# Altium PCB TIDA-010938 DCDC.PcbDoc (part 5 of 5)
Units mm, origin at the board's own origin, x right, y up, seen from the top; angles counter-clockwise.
Board outline 275 x 165 mm, 4 copper layers (Top Layer, Layer 1, Layer 2, Bottom Layer), stack 1.787 mm thick; 436 components, 216 nets, 1367 pads, 1992 vias.
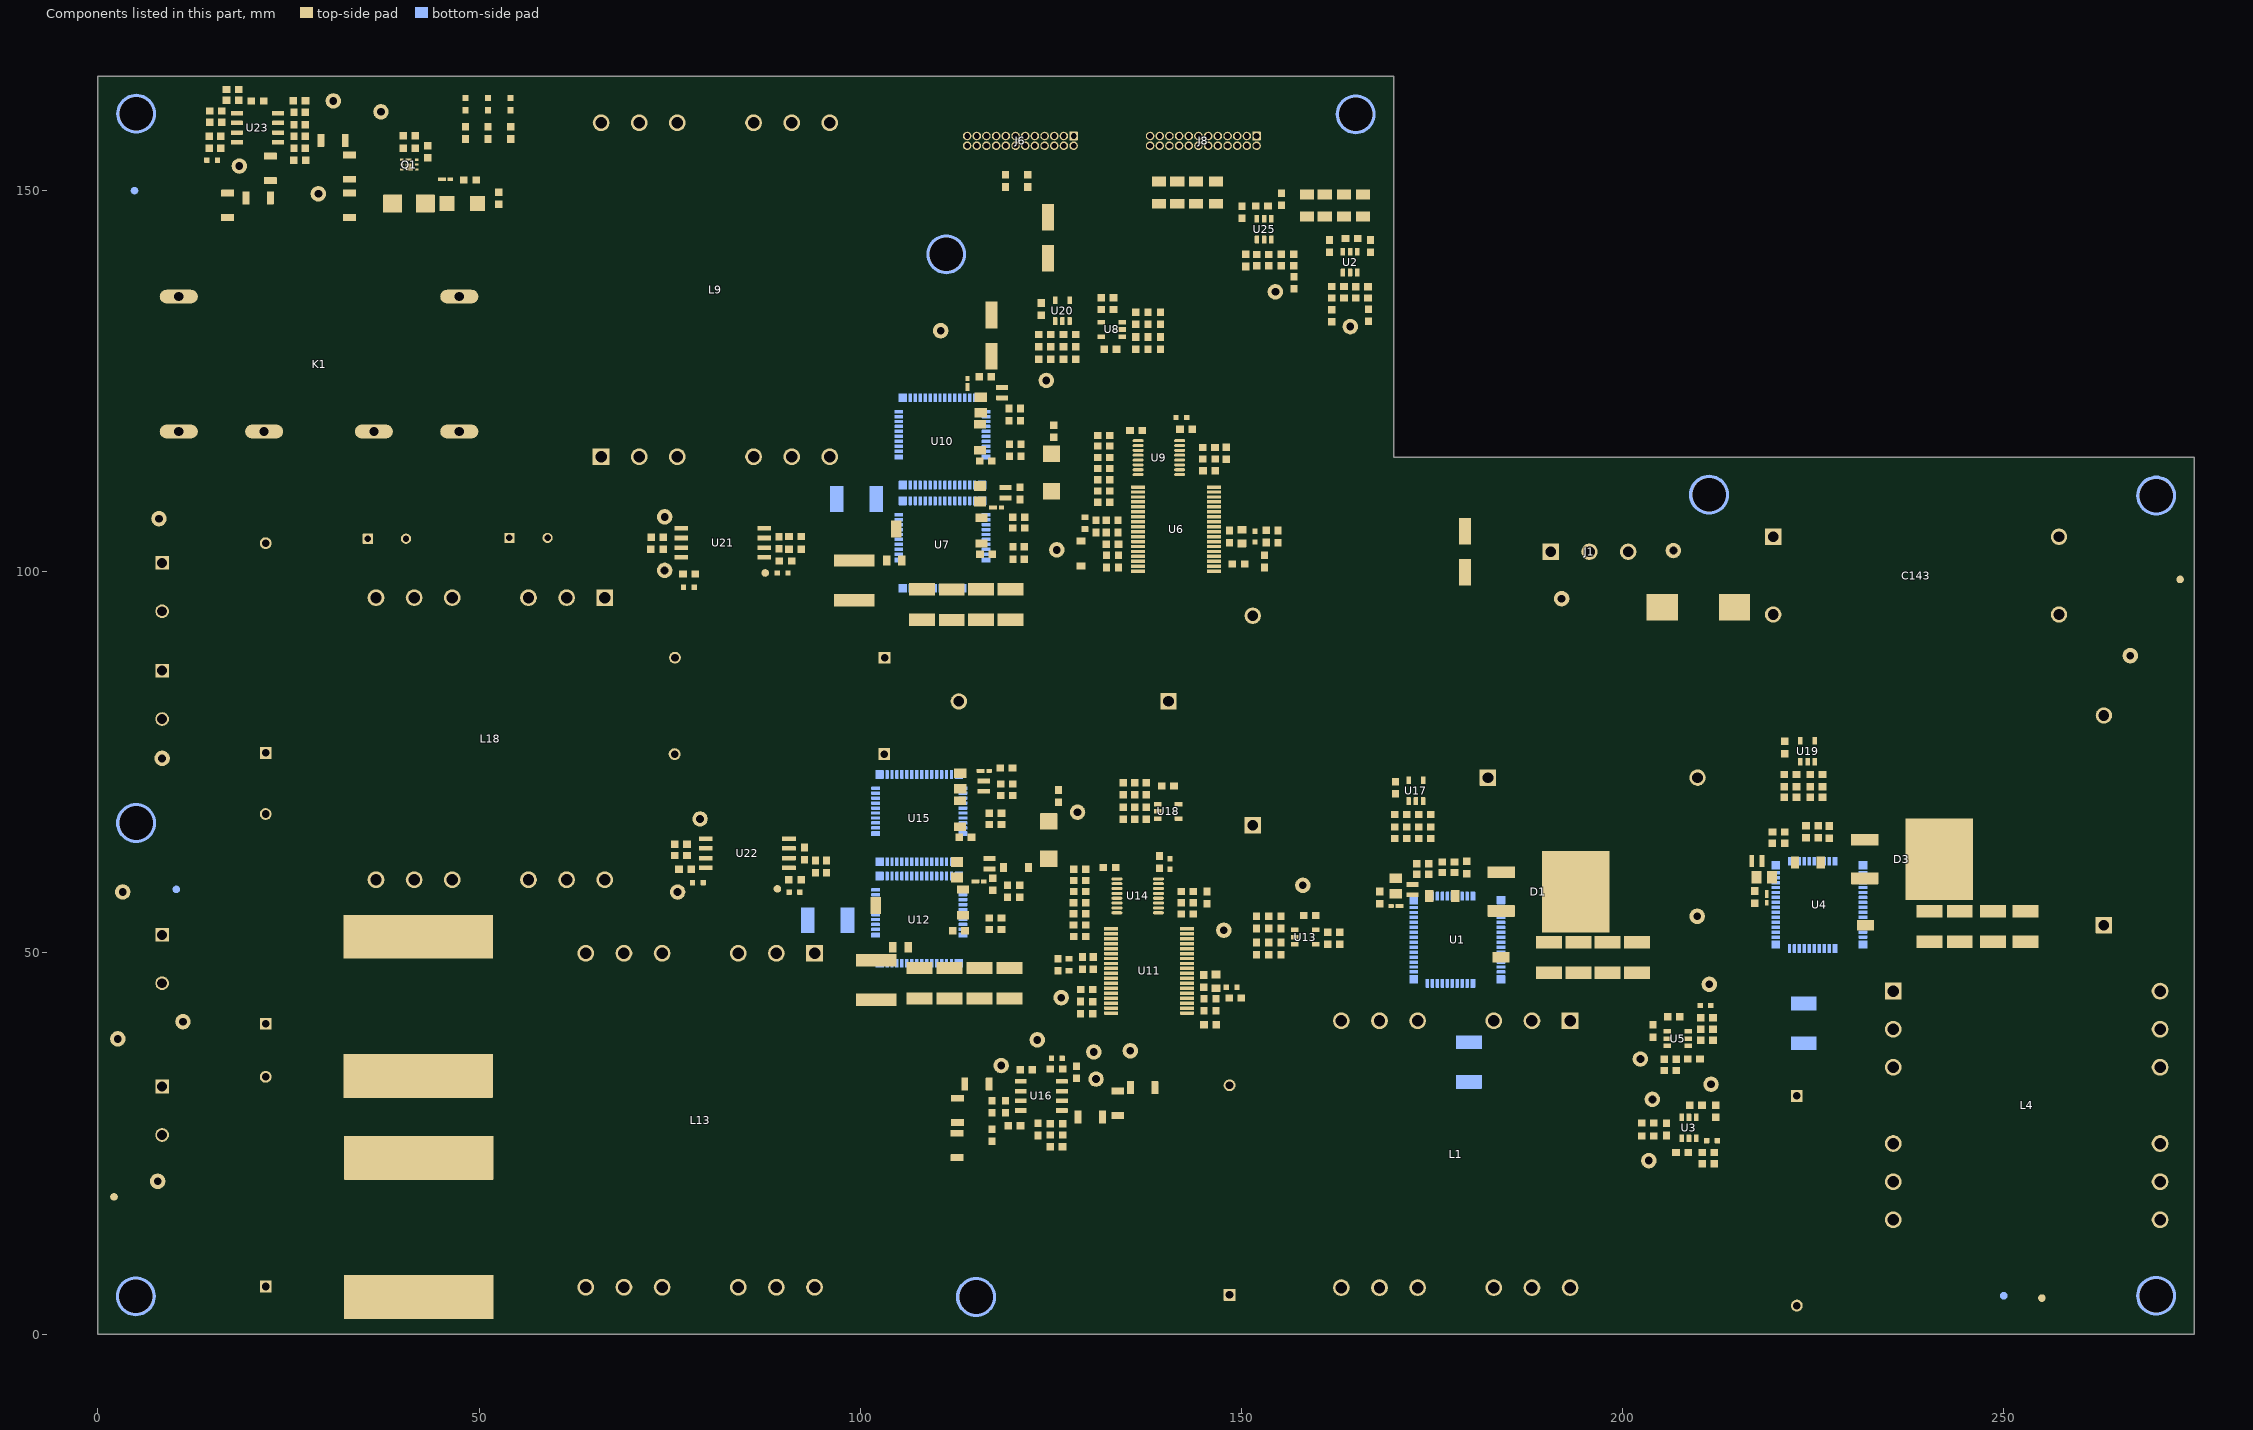
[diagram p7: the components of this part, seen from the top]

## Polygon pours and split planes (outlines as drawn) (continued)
DC_Bus+ on Layer 1 "LAYER_1_DC_BUS+_P054" (solid, remove dead copper, pour order 54): 188.517,68.5 182.279,62.262 182.279,61.241 183.522,59.998 187.559,59.998 189.178,58.378 189.178,51.538 190.472,50.244 203.361,50.244 205.006,51.889 205.006,64.968 201.473,68.5
NetD3_2 on Layer 1 "LAYER_1_NETD3_2_P078" (solid, remove dead copper, pour order 78): 229.901,60.523 229,59.991 229,40 231.216,38.016 237.984,38.016 237.984,41.697 237.984,47.016 234.458,49.649 234.458,59.502 233.485,60.557 233.462,60.535 230.115,60.535
NetD1_2 on Layer 1 "Top Layer-NetD1_2" (solid, remove dead copper, pour order 95): 20 vertices, not listed, extent 181.579,37.987 195.003,56.767
"PV2 Bus-" on Layer 1 "LAYER_1_PV2_BUS-_P001" (solid, remove dead copper, pour order 1): 26 vertices, not listed, extent 1.852,1 229,37.513
Boost1_IN+ on Layer 1 "LAYER_1_BOOST1_IN+_P166" (solid, remove dead copper, pour order 166): 22 vertices, not listed, extent 1.092,46 55.058,70
SW1 on Layer 1 "LAYER_1_SW1_P170" (solid, remove dead copper, pour order 170): 19 vertices, not listed, extent 114.052,100.143 137.625,118.679
SW2 on Layer 1 "LAYER_1_SW2_P174" (solid, remove dead copper, pour order 174): 95.142,57.276 89.165,57.276 88,58.441 88,67.708 88.559,68.267 92.692,68.267 97.153,63.806 97.153,59.288
SW1 on Layer 1 "LAYER_1_SW1_P173" (solid, remove dead copper, pour order 173): 92.907,97.929 86.93,97.929 85.394,99.465 85.394,107.99 86.324,108.92 92.647,108.92 94.918,106.649 94.918,99.94
DC_Bus+ on Layer 1 "LAYER_1_DC_BUS+_P025" (solid, remove dead copper, pour order 25): 37 vertices, not listed, extent 96.725,47.578 144.934,101.04
SW2 on Layer 1 "LAYER_1_SW2_P171" (solid, remove dead copper, pour order 171): 20 vertices, not listed, extent 111.312,41.64 135.151,64.322
DC_Bus- on Bottom Layer "Bottom_Layer-Bat_IN-" (solid, remove dead copper, pour order 163): 112.264,72.123 109.957,74.429 109.957,91.115 122.578,91.115 122.578,93.784 121.782,94.58 104.964,94.58 99.731,89.347 99.731,66.168 111.754,66.168 112.264,66.62
GND_HVN on Bottom Layer "Bottom Layer-GND_HVN" (solid, remove dead copper, pour order 158): 39 vertices, not listed, extent 7.089,56.427 114.316,164.604
DC_Bus+ on Bottom Layer "Bottom Layer-DC_Bus+" (solid, remove dead copper, pour order 55): 54 vertices, not listed, extent 130.01,50.244 273.516,110.074
NetD3_2 on Bottom Layer "Bottom Layer-NetD3_2" (solid, remove dead copper, pour order 74): 229.382,39.41 231.276,37.515 237.923,37.515 238.541,38.133 238.541,48.198 236.964,49.775 233.84,49.775 233.84,60.202 233.193,60.849 230.226,60.849 229.382,60.005 229.382,48.198 229.382,46.083
"BAT Bus-" on Bottom Layer "BOTTOM_LAYER_BAT_BUS-_P108" (solid, remove dead copper, pour order 108): 36 vertices, not listed, extent 3.39,73.669 56.475,121
SW1 on Bottom Layer "BOTTOM_LAYER_SW1_P022" (solid, remove dead copper, pour order 22): 137.536,115.654 137.625,100.293 137.475,100.143 124.644,100.143 123.158,101.59 119.548,101.59 119.548,112.27 125.326,112.27 128.499,115.443 128.499,116.605 130.573,118.679 137.536,118.679
SW2 on Bottom Layer "BOTTOM_LAYER_SW2_P015" (solid, remove dead copper, pour order 15): 17 vertices, not listed, extent 116.501,41.64 135.151,64.322
SW2 on Bottom Layer "gan1_sw" (solid, remove dead copper, pour order 118): 23 vertices, not listed, extent 88,52.689 112.761,68.291
SW1 on Bottom Layer "gan2_sw" (solid, remove dead copper, pour order 119): 38 vertices, not listed, extent 85.394,97.929 115.5,112.356
BatIN+ on Bottom Layer "BOTTOM_LAYER_BATIN+_P169" (solid, remove dead copper, pour order 169): 33 vertices, not listed, extent 54,45 78.17,119
DC_Bus- on Bottom Layer "BOTTOM_LAYER_DC_BUS-_P046" (solid, remove dead copper, pour order 46): 217.556,49.537 219.08,48.014 227.382,48.014 227.382,59.806 226.164,61.183 222.664,61.183 220.93,59.526 219.768,59.526 217.556,57.314
NetL9_6 on Bottom Layer "BOTTOM_LAYER_NETL9_6_P099" (solid, remove dead copper, pour order 99): 97.541,107.2 97.259,106.918 94.437,106.918 94.437,115.717 95.425,116.704 97.541,116.704 98.491,115.754 98.491,113.733 97.541,112.783 97.541,112.699
DC_Bus- on Bottom Layer "BOTTOM_LAYER_DC_BUS-_P061" (solid, remove dead copper, pour order 61): 102.189,124.254 103.532,125.597 111.707,125.597 114,123.304 114,122.013 114.009,122.013 114.446,121.556 114.446,116.796 113.049,115.561 103.421,115.561 102.189,116.793
DC_Bus- on Bottom Layer "BOTTOM_LAYER_DC_BUS-_P125" (solid, remove dead copper, pour order 125): 149.167,54.394 150.112,53.467 150.112,49.67 148.362,47.92 148.362,46.67 142.862,46.67 142.862,53.627 142.679,53.809 140.04,53.809 138.45,55.4 138.499,55.45 140.058,55.45 141.139,54.368 141.165,54.394
DC_Bus+ on Bottom Layer "BOTTOM_LAYER_DC_BUS+_P027" (solid, remove dead copper, pour order 27): 105.788,50.104 107.03,51.346 107.03,51.419 109.35,51.419 110.2,50.57 120.43,50.57 120.43,47.125 103.271,47.125 103.271,49.788 103.586,50.104
DC_Bus- on Bottom Layer "BOTTOM_LAYER_DC_BUS-_P045" (solid, remove dead copper, pour order 45): 180.113,46.777 179.937,46.6 179.991,46.546 179.991,44.35 171.785,44.35 170.348,45.787 170.348,53.998 171.293,54.942 173.254,54.942 173.661,55.349 175.145,56.767 178.342,56.767 180.113,54.765
"PV1 Bus+" on Bottom Layer "BOTTOM_LAYER_PV1_BUS+_P003" (solid, remove dead copper, pour order 3): 18 vertices, not listed, extent 30.975,12.957 170,43.263
DC_Bus+ on Bottom Layer "BOTTOM_LAYER_DC_BUS+_P120" (solid, remove dead copper, pour order 120): 104.315,99.87 110.21,99.87 110.987,100.647 113.839,100.647 115.323,99.163 122.21,99.163 122.845,98.528 122.845,96.334 118.152,96.334 118.145,96.341 116.775,96.341 105.141,96.341 103.806,97.675 103.806,99.362
NetL13_1 on Bottom Layer "BOTTOM_LAYER_NETL13_1_P085" (solid, remove dead copper, pour order 85): 96.381,50.591 96.381,48.636 95.219,47.474 92.464,47.474 92.464,47.494 91.392,48.566 91.392,50.463 90.304,51.55 90.304,54.676 91.437,55.808 94,55.808 94,52.972
Boost1_IN+ on Bottom Layer "BOTTOM_LAYER_BOOST1_IN+_P110" (solid, remove dead copper, pour order 110): 22 vertices, not listed, extent 1.092,46 55.058,70
NetD1_2 on Bottom Layer "Bottom Layer-NetD1_2" (solid, remove dead copper, pour order 97): 21 vertices, not listed, extent 181.711,37.987 195.003,56.767
DC_Bus- on Bottom Layer "BOTTOM_LAYER_DC_BUS-_P071" (solid, remove dead copper, pour order 71): 178.237,38.041 177.936,38.342 177.936,40.037 178.668,40.769 180.931,40.769 181.656,40.045 181.656,38.236 181.461,38.041
DC_Bus- on Bottom Layer "BOTTOM_LAYER_DC_BUS-_P068" (solid, remove dead copper, pour order 68): 222.579,43.014 221.926,43.668 221.926,45.363 222.658,46.095 224.921,46.095 225.646,45.37 225.646,43.562 225.097,43.014
"PV2 Bus-" on Bottom Layer "BOTTOM_LAYER_PV2_BUS-_P069" (solid, remove dead copper, pour order 69): 225.42,38.329 225.721,38.028 225.721,36.333 224.989,35.601 222.726,35.601 222.001,36.325 222.001,38.134 222.196,38.329
"PV1 Bus-" on Bottom Layer "BOTTOM_LAYER_PV1_BUS-_P072" (solid, remove dead copper, pour order 72): 180.954,33.48 181.731,32.703 181.731,31.007 180.999,30.275 178.736,30.275 178.012,31 178.012,32.808 178.683,33.48
"BAT Bus+" on Layer 2 (solid, remove dead copper, pour order 191): 18 vertices, not listed, extent 4.993,92.39 18,146.815
DC_Bus- on Layer 2 (solid, remove dead copper, pour order 190): 83 vertices, not listed, extent 111.006,24.738 272.847,107.006
GND_HVN on Layer 2 "LAYER_2_GND_HVN_P147" (solid, remove dead copper, pour order 147): 20 vertices, not listed, extent 121.011,90.981 179.226,154.748
DC_Bus- on Layer 2 "Layer 2-Bat_IN-" (solid, remove dead copper, pour order 40): 36 vertices, not listed, extent 94.909,41.29 121.818,125.597
BatIN+ on Layer 2 "LAYER_2_BATIN+_P008" (solid, remove dead copper, pour order 8): 33 vertices, not listed, extent 54,45 78.17,119
"PV1 Bus-" on Layer 2 "LAYER_2_PV1_BUS-_P004" (solid, remove dead copper, pour order 4): 31 vertices, not listed, extent 4.6,2 187,48.5
"BAT Bus-" on Layer 2 "LAYER_2_BAT_BUS-_P117" (solid, remove dead copper, pour order 117): 34.018,120 34.075,120.057 39.036,120.057 39.036,120.014 40.05,119 40.05,117.014 39.036,116 33.024,116 33.024,116.006 32.029,117 32.029,127.753 32.029,146.556 33.904,146.556 34.018,146.443
NetC2_2 on Layer 2 "LAYER_2_NETC2_2_P132" (solid, remove dead copper, pour order 132): 19 vertices, not listed, extent 18,94.007 49,121
no net on Bottom Solder "BOTTOM_LAYER_NONET_P106" (solid): 201.815,90.575 207.571,84.818 207.571,55.048 203.065,50.542 189.677,50.542 188.455,51.763 188.455,90.575
no net on Bottom Solder "BOTTOM_LAYER_NONET_P106" (solid): 249.592,95.094 255.349,89.338 255.349,59.568 250.842,55.061 237.454,55.061 236.232,56.283 236.232,95.094

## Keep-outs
Keep-Out Layer:
  the board outline again, w0.5

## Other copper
Top Layer:
  pour cut-out: 211.324,103.147 cw(c211.324,110.147) 204.324,110.147 cw(c211.324,110.147) 211.324,117.147 cw(c211.324,110.147) 218.324,110.147 cw(c211.324,110.147)
  pour cut-out: 75.693,73.082 cw(c75.693,76.082) 72.693,76.082 cw(c75.693,76.082) 75.693,79.082 cw(c75.693,76.082) 78.693,76.082 cw(c75.693,76.082)
  pour cut-out: 75.743,85.73 cw(c75.743,88.73) 72.743,88.73 cw(c75.743,88.73) 75.743,91.73 cw(c75.743,88.73) 78.743,88.73 cw(c75.743,88.73)
  pour cut-out: 111.208,134.727 cw(c111.208,141.727) 104.208,141.727 cw(c111.208,141.727) 111.208,148.727 cw(c111.208,141.727) 118.208,141.727 cw(c111.208,141.727)
  pour cut-out: 151.46,59.762 cw(c151.46,66.762) 144.46,66.762 cw(c151.46,66.762) 151.46,73.762 cw(c151.46,66.762) 158.46,66.762 cw(c151.46,66.762)
  pour cut-out: 111.184,4.869 ccw(c115.184,4.869) 115.184,0.869 ccw(c115.184,4.869) 119.184,4.869 ccw(c115.184,4.869) 115.184,8.869 ccw(c115.184,4.869)
  pour cut-out: 90,49.958 ccw(c94,49.958) 94,45.958 ccw(c94,49.958) 98,49.958 ccw(c94,49.958) 94,53.958 ccw(c94,49.958)
  pour cut-out: 60,49.958 ccw(c64,49.958) 64,45.958 ccw(c64,49.958) 68,49.958 ccw(c64,49.958) 64,53.958 ccw(c64,49.958)
  pour cut-out: 85,49.958 ccw(c89,49.958) 89,45.958 ccw(c89,49.958) 93,49.958 ccw(c89,49.958) 89,53.958 ccw(c89,49.958)
  pour cut-out: 80,49.958 ccw(c84,49.958) 84,45.958 ccw(c84,49.958) 88,49.958 ccw(c84,49.958) 84,53.958 ccw(c84,49.958)
  pour cut-out: 70,49.958 ccw(c74,49.958) 74,45.958 ccw(c74,49.958) 78,49.958 ccw(c74,49.958) 74,53.958 ccw(c74,49.958)
  pour cut-out: 65,49.958 ccw(c69,49.958) 69,45.958 ccw(c69,49.958) 73,49.958 ccw(c69,49.958) 69,53.958 ccw(c69,49.958)
  pour cut-out: 62.475,59.611 ccw(c66.475,59.611) 66.475,55.611 ccw(c66.475,59.611) 70.475,59.611 ccw(c66.475,59.611) 66.475,63.611 ccw(c66.475,59.611)
  pour cut-out: 57.475,59.611 ccw(c61.475,59.611) 61.475,55.611 ccw(c61.475,59.611) 65.475,59.611 ccw(c61.475,59.611) 61.475,63.611 ccw(c61.475,59.611)
  pour cut-out: 52.475,59.611 ccw(c56.475,59.611) 56.475,55.611 ccw(c56.475,59.611) 60.475,59.611 ccw(c56.475,59.611) 56.475,63.611 ccw(c56.475,59.611)
  pour cut-out: 218.857,31.246 ccw(c222.857,31.246) 222.857,27.246 ccw(c222.857,31.246) 226.857,31.246 ccw(c222.857,31.246) 222.857,35.246 ccw(c222.857,31.246)
  pour cut-out: 164.11,41.1 ccw(c168.11,41.1) 168.11,37.1 ccw(c168.11,41.1) 172.11,41.1 ccw(c168.11,41.1) 168.11,45.1 ccw(c168.11,41.1)
  pour cut-out: 159.11,41.1 ccw(c163.11,41.1) 163.11,37.1 ccw(c163.11,41.1) 167.11,41.1 ccw(c163.11,41.1) 163.11,45.1 ccw(c163.11,41.1)
  pour cut-out: 169.11,41.1 ccw(c173.11,41.1) 173.11,37.1 ccw(c173.11,41.1) 177.11,41.1 ccw(c173.11,41.1) 173.11,45.1 ccw(c173.11,41.1)
  pour cut-out: 266.503,45 ccw(c270.503,45) 270.503,41 ccw(c270.503,45) 274.503,45 ccw(c270.503,45) 270.503,49 ccw(c270.503,45)
  pour cut-out: 266.503,40 ccw(c270.503,40) 270.503,36 ccw(c270.503,40) 274.503,40 ccw(c270.503,40) 270.503,44 ccw(c270.503,40)
  pour cut-out: 266.503,35 ccw(c270.503,35) 270.503,31 ccw(c270.503,35) 274.503,35 ccw(c270.503,35) 270.503,39 ccw(c270.503,35)
  pour cut-out: 266.503,25 ccw(c270.503,25) 270.503,21 ccw(c270.503,25) 274.503,25 ccw(c270.503,25) 270.503,29 ccw(c270.503,25)
  pour cut-out: 266.503,20 ccw(c270.503,20) 270.503,16 ccw(c270.503,20) 274.503,20 ccw(c270.503,20) 270.503,24 ccw(c270.503,20)
  pour cut-out: 266.503,15 ccw(c270.503,15) 270.503,11 ccw(c270.503,15) 274.503,15 ccw(c270.503,15) 270.503,19 ccw(c270.503,15)
  pour cut-out: 144.439,5.144 ccw(c148.439,5.144) 148.439,1.144 ccw(c148.439,5.144) 152.439,5.144 ccw(c148.439,5.144) 148.439,9.144 ccw(c148.439,5.144)
  pour cut-out: 3.8,26.125 ccw(c7.8,26.125) 7.8,22.125 ccw(c7.8,26.125) 11.8,26.125 ccw(c7.8,26.125) 7.8,30.125 ccw(c7.8,26.125)
  pour cut-out: 18,40.725 ccw(c22,40.725) 22,36.725 ccw(c22,40.725) 26,40.725 ccw(c22,40.725) 22,44.725 ccw(c22,40.725)
  pour cut-out: 87,114.832 ccw(c91,114.832) 91,110.832 ccw(c91,114.832) 95,114.832 ccw(c91,114.832) 91,118.832 ccw(c91,114.832)
  pour cut-out: 82,115.1 ccw(c86,115.1) 86,111.1 ccw(c86,115.1) 90,115.1 ccw(c86,115.1) 86,119.1 ccw(c86,115.1)
  pour cut-out: 72,115.1 ccw(c76,115.1) 76,111.1 ccw(c76,115.1) 80,115.1 ccw(c76,115.1) 76,119.1 ccw(c76,115.1)
  pour cut-out: 67,115.1 ccw(c71,115.1) 71,111.1 ccw(c71,115.1) 75,115.1 ccw(c71,115.1) 71,119.1 ccw(c71,115.1)
  pour cut-out: 92,158.9 ccw(c96,158.9) 96,154.9 ccw(c96,158.9) 100,158.9 ccw(c96,158.9) 96,162.9 ccw(c96,158.9)
  pour cut-out: 87,158.9 ccw(c91,158.9) 91,154.9 ccw(c91,158.9) 95,158.9 ccw(c91,158.9) 91,162.9 ccw(c91,158.9)
  pour cut-out: 82,158.9 ccw(c86,158.9) 86,154.9 ccw(c86,158.9) 90,158.9 ccw(c86,158.9) 86,162.9 ccw(c86,158.9)
  pour cut-out: 72,158.9 ccw(c76,158.9) 76,154.9 ccw(c76,158.9) 80,158.9 ccw(c76,158.9) 76,162.9 ccw(c76,158.9)
  pour cut-out: 67,158.9 ccw(c71,158.9) 71,154.9 ccw(c71,158.9) 75,158.9 ccw(c71,158.9) 71,162.9 ccw(c71,158.9)
  pour cut-out: 62,158.9 ccw(c66,158.9) 66,154.9 ccw(c66,158.9) 70,158.9 ccw(c66,158.9) 66,162.9 ccw(c66,158.9)
  pour cut-out: 4.881,60.17 cw(c4.881,67.17) -2.119,67.17 cw(c4.881,67.17) 4.881,74.17 cw(c4.881,67.17) 11.881,67.17 cw(c4.881,67.17)
  pour cut-out: 4.948,153.163 cw(c4.948,160.163) -2.052,160.163 cw(c4.948,160.163) 4.948,167.163 cw(c4.948,160.163) 11.948,160.163 cw(c4.948,160.163)
  pour cut-out: 4.952,-2.016 cw(c4.952,4.984) -2.048,4.984 cw(c4.952,4.984) 4.952,11.984 cw(c4.952,4.984) 11.952,4.984 cw(c4.952,4.984)
  pour cut-out: 269.911,-1.891 cw(c269.911,5.109) 262.911,5.109 cw(c269.911,5.109) 269.911,12.109 cw(c269.911,5.109) 276.911,5.109 cw(c269.911,5.109)
  pour cut-out: 269.981,103.024 cw(c269.981,110.024) 262.981,110.024 cw(c269.981,110.024) 269.981,117.024 cw(c269.981,110.024) 276.981,110.024 cw(c269.981,110.024)
  pour cut-out: 164.966,153.041 cw(c164.966,160.041) 157.966,160.041 cw(c164.966,160.041) 164.966,167.041 cw(c164.966,160.041) 171.966,160.041 cw(c164.966,160.041)
  pour cut-out: 115.165,-2.107 cw(c115.165,4.893) 108.165,4.893 cw(c115.165,4.893) 115.165,11.893 cw(c115.165,4.893) 122.165,4.893 cw(c115.165,4.893)
  pour cut-out: 51.753,106.681 56.197,106.681 56.253,106.625 56.253,102.202 51.793,102.202
  pour cut-out: 160.282,9.273 160.282,2.927 196.124,2.927 196.124,9.273
  pour cut-out: 61.172,9.331 61.172,2.985 97.014,2.985 97.014,9.331
  pour cut-out: 38.41,106.443 42.789,106.443 42.845,106.387 42.845,102.077 38.507,102.077 38.424,102.16
  text ".Layer_Name" at -2.5,-161.806 h1.52
Layer 1:
  pour cut-out: 111.184,4.869 ccw(c115.184,4.869) 115.184,0.869 ccw(c115.184,4.869) 119.184,4.869 ccw(c115.184,4.869) 115.184,8.869 ccw(c115.184,4.869)
  pour cut-out: 112.933,81 cw(c112.933,83) 110.933,83 cw(c112.933,83) 112.933,85 cw(c112.933,83) 114.933,83 cw(c112.933,83)
  pour cut-out: 111.261,138.703 cw(c111.261,141.703) 108.261,141.703 cw(c111.261,141.703) 111.261,144.703 cw(c111.261,141.703) 114.261,141.703 cw(c111.261,141.703)
  pour cut-out: 5.001,157.139 cw(c5.001,160.139) 2.001,160.139 cw(c5.001,160.139) 5.001,163.139 cw(c5.001,160.139) 8.001,160.139 cw(c5.001,160.139)
  pour cut-out: 147.479,66.738 ccw(c151.479,66.738) 151.479,62.738 ccw(c151.479,66.738) 155.479,66.738 ccw(c151.479,66.738) 151.479,70.738 ccw(c151.479,66.738)
  pour cut-out: 111.184,4.869 ccw(c115.184,4.869) 115.184,0.869 ccw(c115.184,4.869) 119.184,4.869 ccw(c115.184,4.869) 115.184,8.869 ccw(c115.184,4.869)
  pour cut-out: 90,49.958 ccw(c94,49.958) 94,45.958 ccw(c94,49.958) 98,49.958 ccw(c94,49.958) 94,53.958 ccw(c94,49.958)
  pour cut-out: 60,49.958 ccw(c64,49.958) 64,45.958 ccw(c64,49.958) 68,49.958 ccw(c64,49.958) 64,53.958 ccw(c64,49.958)
  pour cut-out: 85,49.958 ccw(c89,49.958) 89,45.958 ccw(c89,49.958) 93,49.958 ccw(c89,49.958) 89,53.958 ccw(c89,49.958)
  pour cut-out: 80,49.958 ccw(c84,49.958) 84,45.958 ccw(c84,49.958) 88,49.958 ccw(c84,49.958) 84,53.958 ccw(c84,49.958)
  pour cut-out: 70,49.958 ccw(c74,49.958) 74,45.958 ccw(c74,49.958) 78,49.958 ccw(c74,49.958) 74,53.958 ccw(c74,49.958)
  pour cut-out: 65,49.958 ccw(c69,49.958) 69,45.958 ccw(c69,49.958) 73,49.958 ccw(c69,49.958) 69,53.958 ccw(c69,49.958)
  pour cut-out: 231.503,20 ccw(c235.503,20) 235.503,16 ccw(c235.503,20) 239.503,20 ccw(c235.503,20) 235.503,24 ccw(c235.503,20)
  pour cut-out: 231.503,15 ccw(c235.503,15) 235.503,11 ccw(c235.503,15) 239.503,15 ccw(c235.503,15) 235.503,19 ccw(c235.503,15)
  pour cut-out: 218.857,3.746 ccw(c222.857,3.746) 222.857,-0.254 ccw(c222.857,3.746) 226.857,3.746 ccw(c222.857,3.746) 222.857,7.746 ccw(c222.857,3.746)
  pour cut-out: 164.11,41.1 ccw(c168.11,41.1) 168.11,37.1 ccw(c168.11,41.1) 172.11,41.1 ccw(c168.11,41.1) 168.11,45.1 ccw(c168.11,41.1)
  pour cut-out: 159.11,41.1 ccw(c163.11,41.1) 163.11,37.1 ccw(c163.11,41.1) 167.11,41.1 ccw(c163.11,41.1) 163.11,45.1 ccw(c163.11,41.1)
  pour cut-out: 169.11,41.1 ccw(c173.11,41.1) 173.11,37.1 ccw(c173.11,41.1) 177.11,41.1 ccw(c173.11,41.1) 173.11,45.1 ccw(c173.11,41.1)
  pour cut-out: 231.503,25 ccw(c235.503,25) 235.503,21 ccw(c235.503,25) 239.503,25 ccw(c235.503,25) 235.503,29 ccw(c235.503,25)
  pour cut-out: 266.503,45 ccw(c270.503,45) 270.503,41 ccw(c270.503,45) 274.503,45 ccw(c270.503,45) 270.503,49 ccw(c270.503,45)
  pour cut-out: 266.503,40 ccw(c270.503,40) 270.503,36 ccw(c270.503,40) 274.503,40 ccw(c270.503,40) 270.503,44 ccw(c270.503,40)
  pour cut-out: 266.503,35 ccw(c270.503,35) 270.503,31 ccw(c270.503,35) 274.503,35 ccw(c270.503,35) 270.503,39 ccw(c270.503,35)
  pour cut-out: 266.503,25 ccw(c270.503,25) 270.503,21 ccw(c270.503,25) 274.503,25 ccw(c270.503,25) 270.503,29 ccw(c270.503,25)
  pour cut-out: 266.503,20 ccw(c270.503,20) 270.503,16 ccw(c270.503,20) 274.503,20 ccw(c270.503,20) 270.503,24 ccw(c270.503,20)
  pour cut-out: 266.503,15 ccw(c270.503,15) 270.503,11 ccw(c270.503,15) 274.503,15 ccw(c270.503,15) 270.503,19 ccw(c270.503,15)
  pour cut-out: 144.439,5.144 ccw(c148.439,5.144) 148.439,1.144 ccw(c148.439,5.144) 152.439,5.144 ccw(c148.439,5.144) 148.439,9.144 ccw(c148.439,5.144)
  pour cut-out: 3.8,32.475 ccw(c7.8,32.475) 7.8,28.475 ccw(c7.8,32.475) 11.8,32.475 ccw(c7.8,32.475) 7.8,36.475 ccw(c7.8,32.475)
  pour cut-out: 18,33.75 ccw(c22,33.75) 22,29.75 ccw(c22,33.75) 26,33.75 ccw(c22,33.75) 22,37.75 ccw(c22,33.75)
  pour cut-out: 18,40.725 ccw(c22,40.725) 22,36.725 ccw(c22,40.725) 26,40.725 ccw(c22,40.725) 22,44.725 ccw(c22,40.725)
  pour cut-out: 4,94.825 ccw(c8,94.825) 8,90.825 ccw(c8,94.825) 12,94.825 ccw(c8,94.825) 8,98.825 ccw(c8,94.825)
  pour cut-out: 4,101.175 ccw(c8,101.175) 8,97.175 ccw(c8,101.175) 12,101.175 ccw(c8,101.175) 8,105.175 ccw(c8,101.175)
  pour cut-out: 54.043,98.944 68.997,98.944 68.997,94.074 54.043,94.074
  pour cut-out: 160.282,9.273 160.282,2.927 196.124,2.927 196.124,9.273
  pour cut-out: 61.172,9.331 61.172,2.985 97.014,2.985 97.014,9.331
  pour cut-out: 105.916,138.235 107.947,136.205 113.692,136.205 116.395,138.908 116.395,143.672 112.94,147.127 108.856,147.005 105.916,144.065
  pour cut-out: 62.827,161.335 99.173,161.335 99.173,156.465 62.827,156.465
  pour cut-out: 29.95,147.45 29.95,142.95 36.004,142.95 36.004,147.45
  pour cut-out: 13.979,147.418 13.979,142.918 20.032,142.918 20.032,147.418
  pour cut-out: 101.358,77.855 104.96,77.855 104.96,74.309 101.377,74.309
  pour cut-out: 101.408,90.503 105.01,90.503 105.01,86.957 101.427,86.957
Layer 2:
  pour cut-out: 219.32,55.874 220.082,56.635 220.082,61.332 220.834,62.084 227.043,62.084 227.382,61.745 227.382,61.017 224.63,58.264 224.63,57.297 226.886,55.041 237.506,55.041 248.31,55.012 249.239,55.941 249.239,69.588 247.443,71.384 247.37,71.312 234.56,71.312 230.889,74.983 217.932,74.983 217.932,66.586 215.324,63.978 215.324,55.874
  pour cut-out: 140.467,80 cw(c140.467,83) 137.467,83 cw(c140.467,83) 140.467,86 cw(c140.467,83) 143.467,83 cw(c140.467,83)
  pour cut-out: 259.172,53.656 ccw(c263.172,53.656) 263.172,49.656 ccw(c263.172,53.656) 267.172,53.656 ccw(c263.172,53.656) 263.172,57.656 ccw(c263.172,53.656)
  pour cut-out: 111.261,138.703 cw(c111.261,141.703) 108.261,141.703 cw(c111.261,141.703) 111.261,144.703 cw(c111.261,141.703) 114.261,141.703 cw(c111.261,141.703)
  pour cut-out: 5.001,157.139 cw(c5.001,160.139) 2.001,160.139 cw(c5.001,160.139) 5.001,163.139 cw(c5.001,160.139) 8.001,160.139 cw(c5.001,160.139)
  pour cut-out: 111.184,4.869 ccw(c115.184,4.869) 115.184,0.869 ccw(c115.184,4.869) 119.184,4.869 ccw(c115.184,4.869) 115.184,8.869 ccw(c115.184,4.869)
  pour cut-out: 90,49.958 ccw(c94,49.958) 94,45.958 ccw(c94,49.958) 98,49.958 ccw(c94,49.958) 94,53.958 ccw(c94,49.958)
  pour cut-out: 85,49.958 ccw(c89,49.958) 89,45.958 ccw(c89,49.958) 93,49.958 ccw(c89,49.958) 89,53.958 ccw(c89,49.958)
  pour cut-out: 80,49.958 ccw(c84,49.958) 84,45.958 ccw(c84,49.958) 88,49.958 ccw(c84,49.958) 84,53.958 ccw(c84,49.958)
  pour cut-out: 231.503,20 ccw(c235.503,20) 235.503,16 ccw(c235.503,20) 239.503,20 ccw(c235.503,20) 235.503,24 ccw(c235.503,20)
  pour cut-out: 231.503,15 ccw(c235.503,15) 235.503,11 ccw(c235.503,15) 239.503,15 ccw(c235.503,15) 235.503,19 ccw(c235.503,15)
  pour cut-out: 218.857,3.746 ccw(c222.857,3.746) 222.857,-0.254 ccw(c222.857,3.746) 226.857,3.746 ccw(c222.857,3.746) 222.857,7.746 ccw(c222.857,3.746)
  pour cut-out: 218.857,31.246 ccw(c222.857,31.246) 222.857,27.246 ccw(c222.857,31.246) 226.857,31.246 ccw(c222.857,31.246) 222.857,35.246 ccw(c222.857,31.246)
  pour cut-out: 164.11,41.1 ccw(c168.11,41.1) 168.11,37.1 ccw(c168.11,41.1) 172.11,41.1 ccw(c168.11,41.1) 168.11,45.1 ccw(c168.11,41.1)
  pour cut-out: 159.11,41.1 ccw(c163.11,41.1) 163.11,37.1 ccw(c163.11,41.1) 167.11,41.1 ccw(c163.11,41.1) 163.11,45.1 ccw(c163.11,41.1)
  pour cut-out: 231.503,25 ccw(c235.503,25) 235.503,21 ccw(c235.503,25) 239.503,25 ccw(c235.503,25) 235.503,29 ccw(c235.503,25)
  pour cut-out: 266.503,45 ccw(c270.503,45) 270.503,41 ccw(c270.503,45) 274.503,45 ccw(c270.503,45) 270.503,49 ccw(c270.503,45)
  pour cut-out: 266.503,40 ccw(c270.503,40) 270.503,36 ccw(c270.503,40) 274.503,40 ccw(c270.503,40) 270.503,44 ccw(c270.503,40)
  pour cut-out: 266.503,35 ccw(c270.503,35) 270.503,31 ccw(c270.503,35) 274.503,35 ccw(c270.503,35) 270.503,39 ccw(c270.503,35)
  pour cut-out: 266.503,25 ccw(c270.503,25) 270.503,21 ccw(c270.503,25) 274.503,25 ccw(c270.503,25) 270.503,29 ccw(c270.503,25)
  pour cut-out: 266.503,20 ccw(c270.503,20) 270.503,16 ccw(c270.503,20) 274.503,20 ccw(c270.503,20) 270.503,24 ccw(c270.503,20)
  pour cut-out: 266.503,15 ccw(c270.503,15) 270.503,11 ccw(c270.503,15) 274.503,15 ccw(c270.503,15) 270.503,19 ccw(c270.503,15)
  pour cut-out: 189.11,6.1 ccw(c193.11,6.1) 193.11,2.1 ccw(c193.11,6.1) 197.11,6.1 ccw(c193.11,6.1) 193.11,10.1 ccw(c193.11,6.1)
  pour cut-out: 184.11,6.1 ccw(c188.11,6.1) 188.11,2.1 ccw(c188.11,6.1) 192.11,6.1 ccw(c188.11,6.1) 188.11,10.1 ccw(c188.11,6.1)
  pour cut-out: 179.11,6.1 ccw(c183.11,6.1) 183.11,2.1 ccw(c183.11,6.1) 187.11,6.1 ccw(c183.11,6.1) 183.11,10.1 ccw(c183.11,6.1)
  pour cut-out: 169.11,6.1 ccw(c173.11,6.1) 173.11,2.1 ccw(c173.11,6.1) 177.11,6.1 ccw(c173.11,6.1) 173.11,10.1 ccw(c173.11,6.1)
  pour cut-out: 164.11,6.1 ccw(c168.11,6.1) 168.11,2.1 ccw(c168.11,6.1) 172.11,6.1 ccw(c168.11,6.1) 168.11,10.1 ccw(c168.11,6.1)
  pour cut-out: 159.11,6.1 ccw(c163.11,6.1) 163.11,2.1 ccw(c163.11,6.1) 167.11,6.1 ccw(c163.11,6.1) 163.11,10.1 ccw(c163.11,6.1)
  pour cut-out: 90,6.158 ccw(c94,6.158) 94,2.158 ccw(c94,6.158) 98,6.158 ccw(c94,6.158) 94,10.158 ccw(c94,6.158)
  pour cut-out: 85,6.158 ccw(c89,6.158) 89,2.158 ccw(c89,6.158) 93,6.158 ccw(c89,6.158) 89,10.158 ccw(c89,6.158)
  pour cut-out: 80,6.158 ccw(c84,6.158) 84,2.158 ccw(c84,6.158) 88,6.158 ccw(c84,6.158) 84,10.158 ccw(c84,6.158)
  pour cut-out: 70,6.158 ccw(c74,6.158) 74,2.158 ccw(c74,6.158) 78,6.158 ccw(c74,6.158) 74,10.158 ccw(c74,6.158)
  pour cut-out: 65,6.158 ccw(c69,6.158) 69,2.158 ccw(c69,6.158) 73,6.158 ccw(c69,6.158) 69,10.158 ccw(c69,6.158)
  pour cut-out: 60,6.158 ccw(c64,6.158) 64,2.158 ccw(c64,6.158) 68,6.158 ccw(c64,6.158) 64,10.158 ccw(c64,6.158)
  pour cut-out: 18,6.25 ccw(c22,6.25) 22,2.25 ccw(c22,6.25) 26,6.25 ccw(c22,6.25) 22,10.25 ccw(c22,6.25)
  pour cut-out: 3.8,26.125 ccw(c7.8,26.125) 7.8,22.125 ccw(c7.8,26.125) 11.8,26.125 ccw(c7.8,26.125) 7.8,30.125 ccw(c7.8,26.125)
  pour cut-out: 3.8,32.475 ccw(c7.8,32.475) 7.8,28.475 ccw(c7.8,32.475) 11.8,32.475 ccw(c7.8,32.475) 7.8,36.475 ccw(c7.8,32.475)
  pour cut-out: 18,68.225 ccw(c22,68.225) 22,64.225 ccw(c22,68.225) 26,68.225 ccw(c22,68.225) 22,72.225 ccw(c22,68.225)
  pour cut-out: 92,158.9 ccw(c96,158.9) 96,154.9 ccw(c96,158.9) 100,158.9 ccw(c96,158.9) 96,162.9 ccw(c96,158.9)
  pour cut-out: 87,158.9 ccw(c91,158.9) 91,154.9 ccw(c91,158.9) 95,158.9 ccw(c91,158.9) 91,162.9 ccw(c91,158.9)
  pour cut-out: 82,158.9 ccw(c86,158.9) 86,154.9 ccw(c86,158.9) 90,158.9 ccw(c86,158.9) 86,162.9 ccw(c86,158.9)
  pour cut-out: 72,158.9 ccw(c76,158.9) 76,154.9 ccw(c76,158.9) 80,158.9 ccw(c76,158.9) 76,162.9 ccw(c76,158.9)
  pour cut-out: 67,158.9 ccw(c71,158.9) 71,154.9 ccw(c71,158.9) 75,158.9 ccw(c71,158.9) 71,162.9 ccw(c71,158.9)
  pour cut-out: 62,158.9 ccw(c66,158.9) 66,154.9 ccw(c66,158.9) 70,158.9 ccw(c66,158.9) 66,162.9 ccw(c66,158.9)
  pour cut-out: 144.266,76.63 142.806,78.089 142.806,78.101 129.136,78.101 129.132,78.097 129.132,76.301 130.74,74.537 144.221,74.537 144.471,74.787 144.266,74.993
  pour cut-out: 212.482,37.458 212.482,36.422 213.518,36.422 213.518,37.458
  pour cut-out: 200.42,28.25 200.42,27.215 201.456,27.215 201.456,28.25
  pour cut-out: 51.773,106.671 56.217,106.671 56.273,106.614 56.273,102.192 51.813,102.192
  pour cut-out: 194.553,43.535 197.472,40.616 197.472,37.767 183.934,37.767 181,40.701 181,42.5 182.035,43.535
Bottom Layer:
  pour cut-out: 4.981,60.07 cw(c4.981,67.07) -2.019,67.07 cw(c4.981,67.07) 4.981,74.07 cw(c4.981,67.07) 11.981,67.07 cw(c4.981,67.07)
  pour cut-out: 3.8,26.125 ccw(c7.8,26.125) 7.8,22.125 ccw(c7.8,26.125) 11.8,26.125 ccw(c7.8,26.125) 7.8,30.125 ccw(c7.8,26.125)
  pour cut-out: 259.134,81.156 ccw(c263.134,81.156) 263.134,77.156 ccw(c263.134,81.156) 267.134,81.156 ccw(c263.134,81.156) 263.134,85.156 ccw(c263.134,81.156)
  pour cut-out: 211.374,103.097 cw(c211.374,110.097) 204.374,110.097 cw(c211.374,110.097) 211.374,117.097 cw(c211.374,110.097) 218.374,110.097 cw(c211.374,110.097)
  pour cut-out: 111.184,4.869 ccw(c115.184,4.869) 115.184,0.869 ccw(c115.184,4.869) 119.184,4.869 ccw(c115.184,4.869) 115.184,8.869 ccw(c115.184,4.869)
  pour cut-out: 80,49.958 ccw(c84,49.958) 84,45.958 ccw(c84,49.958) 88,49.958 ccw(c84,49.958) 84,53.958 ccw(c84,49.958)
  pour cut-out: 70,49.958 ccw(c74,49.958) 74,45.958 ccw(c74,49.958) 78,49.958 ccw(c74,49.958) 74,53.958 ccw(c74,49.958)
  pour cut-out: 42.475,96.611 ccw(c46.475,96.611) 46.475,92.611 ccw(c46.475,96.611) 50.475,96.611 ccw(c46.475,96.611) 46.475,100.611 ccw(c46.475,96.611)
  pour cut-out: 37.475,96.611 ccw(c41.475,96.611) 41.475,92.611 ccw(c41.475,96.611) 45.475,96.611 ccw(c41.475,96.611) 41.475,100.611 ccw(c41.475,96.611)
  pour cut-out: 32.475,96.611 ccw(c36.475,96.611) 36.475,92.611 ccw(c36.475,96.611) 40.475,96.611 ccw(c36.475,96.611) 36.475,100.611 ccw(c36.475,96.611)
  pour cut-out: 18,76.25 ccw(c22,76.25) 22,72.25 ccw(c22,76.25) 26,76.25 ccw(c22,76.25) 22,80.25 ccw(c22,76.25)
  pour cut-out: 231.503,20 ccw(c235.503,20) 235.503,16 ccw(c235.503,20) 239.503,20 ccw(c235.503,20) 235.503,24 ccw(c235.503,20)
  pour cut-out: 231.503,15 ccw(c235.503,15) 235.503,11 ccw(c235.503,15) 239.503,15 ccw(c235.503,15) 235.503,19 ccw(c235.503,15)
  pour cut-out: 218.857,3.746 ccw(c222.857,3.746) 222.857,-0.254 ccw(c222.857,3.746) 226.857,3.746 ccw(c222.857,3.746) 222.857,7.746 ccw(c222.857,3.746)
  pour cut-out: 231.503,25 ccw(c235.503,25) 235.503,21 ccw(c235.503,25) 239.503,25 ccw(c235.503,25) 235.503,29 ccw(c235.503,25)
  pour cut-out: 266.503,45 ccw(c270.503,45) 270.503,41 ccw(c270.503,45) 274.503,45 ccw(c270.503,45) 270.503,49 ccw(c270.503,45)
  pour cut-out: 266.503,40 ccw(c270.503,40) 270.503,36 ccw(c270.503,40) 274.503,40 ccw(c270.503,40) 270.503,44 ccw(c270.503,40)
  pour cut-out: 266.503,35 ccw(c270.503,35) 270.503,31 ccw(c270.503,35) 274.503,35 ccw(c270.503,35) 270.503,39 ccw(c270.503,35)
  pour cut-out: 266.503,25 ccw(c270.503,25) 270.503,21 ccw(c270.503,25) 274.503,25 ccw(c270.503,25) 270.503,29 ccw(c270.503,25)
  pour cut-out: 266.503,20 ccw(c270.503,20) 270.503,16 ccw(c270.503,20) 274.503,20 ccw(c270.503,20) 270.503,24 ccw(c270.503,20)
  pour cut-out: 266.503,15 ccw(c270.503,15) 270.503,11 ccw(c270.503,15) 274.503,15 ccw(c270.503,15) 270.503,19 ccw(c270.503,15)
  pour cut-out: 189.11,6.1 ccw(c193.11,6.1) 193.11,2.1 ccw(c193.11,6.1) 197.11,6.1 ccw(c193.11,6.1) 193.11,10.1 ccw(c193.11,6.1)
  pour cut-out: 184.11,6.1 ccw(c188.11,6.1) 188.11,2.1 ccw(c188.11,6.1) 192.11,6.1 ccw(c188.11,6.1) 188.11,10.1 ccw(c188.11,6.1)
  pour cut-out: 179.11,6.1 ccw(c183.11,6.1) 183.11,2.1 ccw(c183.11,6.1) 187.11,6.1 ccw(c183.11,6.1) 183.11,10.1 ccw(c183.11,6.1)
  pour cut-out: 169.11,6.1 ccw(c173.11,6.1) 173.11,2.1 ccw(c173.11,6.1) 177.11,6.1 ccw(c173.11,6.1) 173.11,10.1 ccw(c173.11,6.1)
  pour cut-out: 164.11,6.1 ccw(c168.11,6.1) 168.11,2.1 ccw(c168.11,6.1) 172.11,6.1 ccw(c168.11,6.1) 168.11,10.1 ccw(c168.11,6.1)
  pour cut-out: 159.11,6.1 ccw(c163.11,6.1) 163.11,2.1 ccw(c163.11,6.1) 167.11,6.1 ccw(c163.11,6.1) 163.11,10.1 ccw(c163.11,6.1)
  pour cut-out: 144.439,5.144 ccw(c148.439,5.144) 148.439,1.144 ccw(c148.439,5.144) 152.439,5.144 ccw(c148.439,5.144) 148.439,9.144 ccw(c148.439,5.144)
  pour cut-out: 90,6.158 ccw(c94,6.158) 94,2.158 ccw(c94,6.158) 98,6.158 ccw(c94,6.158) 94,10.158 ccw(c94,6.158)
  pour cut-out: 85,6.158 ccw(c89,6.158) 89,2.158 ccw(c89,6.158) 93,6.158 ccw(c89,6.158) 89,10.158 ccw(c89,6.158)
  pour cut-out: 80,6.158 ccw(c84,6.158) 84,2.158 ccw(c84,6.158) 88,6.158 ccw(c84,6.158) 84,10.158 ccw(c84,6.158)
  pour cut-out: 70,6.158 ccw(c74,6.158) 74,2.158 ccw(c74,6.158) 78,6.158 ccw(c74,6.158) 74,10.158 ccw(c74,6.158)
  pour cut-out: 65,6.158 ccw(c69,6.158) 69,2.158 ccw(c69,6.158) 73,6.158 ccw(c69,6.158) 69,10.158 ccw(c69,6.158)
  pour cut-out: 60,6.158 ccw(c64,6.158) 64,2.158 ccw(c64,6.158) 68,6.158 ccw(c64,6.158) 64,10.158 ccw(c64,6.158)
  pour cut-out: 18,6.25 ccw(c22,6.25) 22,2.25 ccw(c22,6.25) 26,6.25 ccw(c22,6.25) 22,10.25 ccw(c22,6.25)
  pour cut-out: 3.8,32.475 ccw(c7.8,32.475) 7.8,28.475 ccw(c7.8,32.475) 11.8,32.475 ccw(c7.8,32.475) 7.8,36.475 ccw(c7.8,32.475)
  pour cut-out: 18,33.75 ccw(c22,33.75) 22,29.75 ccw(c22,33.75) 26,33.75 ccw(c22,33.75) 22,37.75 ccw(c22,33.75)
  pour cut-out: 18,40.725 ccw(c22,40.725) 22,36.725 ccw(c22,40.725) 26,40.725 ccw(c22,40.725) 22,44.725 ccw(c22,40.725)
  pour cut-out: 115.215,-2.157 cw(c115.215,4.843) 108.215,4.843 cw(c115.215,4.843) 115.215,11.843 cw(c115.215,4.843) 122.215,4.843 cw(c115.215,4.843)
  pour cut-out: 5.048,153.063 cw(c5.048,160.063) -1.952,160.063 cw(c5.048,160.063) 5.048,167.063 cw(c5.048,160.063) 12.048,160.063 cw(c5.048,160.063)
  pour cut-out: 5.002,-2.066 cw(c5.002,4.934) -1.998,4.934 cw(c5.002,4.934) 5.002,11.934 cw(c5.002,4.934) 12.002,4.934 cw(c5.002,4.934)
  pour cut-out: 270.011,-1.991 cw(c270.011,5.009) 263.011,5.009 cw(c270.011,5.009) 270.011,12.009 cw(c270.011,5.009) 277.011,5.009 cw(c270.011,5.009)
  pour cut-out: 270.081,102.924 cw(c270.081,109.924) 263.081,109.924 cw(c270.081,109.924) 270.081,116.924 cw(c270.081,109.924) 277.081,109.924 cw(c270.081,109.924)
  pour cut-out: 165.016,152.991 cw(c165.016,159.991) 158.016,159.991 cw(c165.016,159.991) 165.016,166.991 cw(c165.016,159.991) 172.016,159.991 cw(c165.016,159.991)
  pour cut-out: 111.729,134.677 cw(c111.729,141.677) 104.729,141.677 cw(c111.729,141.677) 111.729,148.677 cw(c111.729,141.677) 118.729,141.677 cw(c111.729,141.677)
  pour cut-out: 62.755,161.23 99.102,161.23 99.102,156.36 62.755,156.36
  pour cut-out: 29.945,147.45 29.945,142.95 35.998,142.95 35.998,147.45
  pour cut-out: 14,147.5 14,143 20.053,143 20.053,147.5
  text ".Layer_Name" at -10.344,-161.806 h1.52

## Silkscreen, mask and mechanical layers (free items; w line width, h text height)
Top Overlay:
  text "12V" at 46.605,162.913 h0.5
  text "5V" at 49.81,162.913 h0.5
  text "3V3" at 52.598,162.913 h0.5
  text "+" at 124.542,149.371 h0.5
  text "-" at 124.51,138.227 h0.5
  text "+" at 118.497,135.17 h0.5
  text "-" at 118.52,126.656 h0.5
  text ".PRJ_Number" at 170.375,111.688 h3.05
  text "VER: .PCB_Rev" at 197.288,111.702 h3.05
  text "18/08/2023" at 170.97,108.753 h3.05
  text "DC+" at 186.928,108.065 h2
  text "DC-" at 200.5,108.065 h2
  text "-" at 178.652,107.76 h0.5 r180
  text "BAT+" at 0.918,105.447 h2
  text "1" at 190.037,104.485 h0.5
  text "1" at 7.99,102.831 h0.5
  text "+" at 178.726,97.568 h0.5 r180
  text "BAT-" at 0.706,75.022 h2
  text "1" at 7.863,68.547 h0.5
  text "PV1+" at 5.567,56 h2
  text "PV1-" at 5.365,40.594 h2
  text "PV2+" at 5.718,36.7 h2
  text "1" at 7.489,34.131 h0.5
  text "PV2-" at 2.107,21 h2
  text ".Layer_Name" at -10.344,-161.806 h0.5
Bottom Overlay:
  text ".Layer_Name" at -10.344,-161.806 h0.5
Top Paste:
  text ".Layer_Name" at -10.344,-161.806 h1.52
Bottom Paste:
  text ".Layer_Name" at -10.344,-161.806 h1.52
Top Solder:
  text ".Layer_Name" at -10.344,-161.806 h1.52
  text ".Layer_Name" at -10.344,-161.806 h1.52
Bottom Solder:
  text ".Layer_Name" at -10.344,-161.806 h1.52
M1 Board Outline:
  region: 183.95,125.103 183.954,125.144 183.891,125.15 183.887,125.109
  lines w0.5: 0,0 0,165 ; 0,0 275,0 ; 0,0 0,165 ; 0,0 275,0 ; 0,165 170,165 ; 0,165 170,165 ; 170,115 170,165 ; 170,115 275,115 ; 170,115 170,165 ; 170,115 275,115 ; 275,0 275,115 ; 275,0 275,115
  text ".Layer_Name" at -0.5,-9 h1.52
M2 Board Dimensions:
  rectangle: -21.825,-150.16 -12.3,-146.985
  rectangle: -25,-146.985 -21.825,-143.81
  lines w0.178: -25,-146.985 0.4,-146.985 ; -21.825,-150.16 -21.825,-143.81 ; -18.65,-150.16 -18.65,-143.81 ; -12.3,-150.16 -12.3,-143.81 ; -5.95,-150.16 -5.95,-143.81 ; -25,-150.16 -25,-143.81 0.4,-143.81 0.4,-150.16 -25,-150.16
  text ".Layer_Name" at -7.5,-161.806 h1.52
M3 3D STEP Top:
  text ".Layer_Name" at -10.344,-161.806 h1.52
M4 3D STEP Bottom:
  text ".Layer_Name" at -10.344,-161.806 h1.52
M5 Assembly Top:
  lines w0.254: -32.417,-163.626 135.223,-163.626 ; -32.417,-158.462 135.274,-158.462 ; -32.417,-153.297 -32.417,-168.791 69.31,-168.791 135.274,-168.791 135.274,-153.297 -32.404,-153.297 -32.404,-168.791 7.614,-168.791 ; 30.194,-168.791 30.194,-153.297 ; 62.376,-158.462 62.376,-153.297 ; 83.712,-158.462 83.712,-153.297 ; 99.511,-168.956 99.511,-163.804
  text "COMPONENTS MARKED 'DNP' SHOULD NOT BE POPULATED." at 4.299,-148.09 h1.52
  text "ASSEMBLY VARIANT:" at 4.286,-151.024 h1.52
  text ".VariantName" at 30.601,-151.024 h1.52
  text "PCB VIEWED FROM TOP SIDE" at -30.804,-156.654 h1.52
  text "BOARD #:" at 32.099,-156.654 h1.52
  text ".PRJ_Number" at 45.955,-156.654 h1.52
  text "REV:" at 67.405,-156.654 h1.52
  text ".PCB_Rev" at 74.809,-156.654 h1.52
  text "SVN REV:" at 88.69,-156.654 h1.52
  text ".VersionControl_RevNumber" at 101.543,-156.654 h1.52
  text "PLOT NAME =" at -30.804,-167.034 h1.52
  text ".plot_File_Name" at -10.344,-167.034 h1.52
  text "GENERATED    :" at 32.15,-167.034 h1.52
  text ".Print_Date" at 54.235,-167.034 h1.52
  text ".Print_Time" at 72.752,-167.034 h1.52
  text "TEXAS INSTRUMENTS" at 104.87,-167.034 h1.52
M6 Assembly Bottom:
  lines w0.254: -32.429,-158.474 135.261,-158.474 ; -32.379,-163.639 135.261,-163.639 ; 3.334,-168.969 3.334,-163.817 ; 19.133,-158.474 19.133,-153.31 ; 40.469,-158.474 40.469,-153.31 ; 72.65,-168.804 72.65,-153.31 ; 95.231,-168.804 135.249,-168.804 135.249,-153.31 -32.429,-153.31 -32.429,-168.804 33.534,-168.804 135.261,-168.804 135.261,-153.31
  text "COMPONENTS MARKED 'DNP' SHOULD NOT BE POPULATED." at 129.991,-148.077 h1.52
  text ".VariantName" at 103.473,-151.024 h1.52
  text "ASSEMBLY VARIANT:" at 129.864,-151.024 h1.52
  text ".VersionControl_RevNumber" at 1.302,-156.667 h1.52
  text "SVN REV:" at 14.154,-156.667 h1.52
  text ".PCB_Rev" at 28.035,-156.667 h1.52
  text "REV:" at 35.439,-156.667 h1.52
  text ".PRJ_Number" at 56.89,-156.667 h1.52
  text "BOARD #:" at 70.745,-156.667 h1.52
  text "PCB VIEWED FROM BOTTOM SIDE" at 133.648,-156.667 h1.52
  text "TEXAS INSTRUMENTS" at -2.026,-167.047 h1.52
  text ".Print_Time" at 30.093,-167.047 h1.52
  text ".Print_Date" at 48.609,-167.047 h1.52
  text "GENERATED    :" at 70.695,-167.047 h1.52
  text ".plot_File_Name" at 113.189,-167.047 h1.52
  text "PLOT NAME =" at 133.648,-167.047 h1.52
M7 LPKF Text Top:
  text "Venkatesh" at 237.071,85.788 h1.52
M9 Title Sheet:
  drawing of 56 lines, arcs and shapes, not listed
  text "1" at 1.882,199.887 h1.78
  text "2" at 86.354,199.887 h1.78
  text "3" at 170.936,199.887 h1.78
  text "4" at 255.645,199.887 h1.78
  text "5" at 340.1,199.887 h1.78
  text "6" at 424.809,199.887 h1.78
  text "A" at -36.76,154.726 h1.78
  text "A" at 463.62,154.726 h1.78
  text "B" at -36.76,59.476 h1.78
  text "B" at 463.62,59.476 h1.78
  text "C" at -36.76,-35.774 h1.78
  text "C" at 463.62,-35.774 h1.78
  text "D" at -36.76,-131.024 h1.78
  text "D" at 463.62,-131.024 h1.78
  text "PROJECT TITLE:" at 385.032,-133.183 h1.14
  text ".PRJ_Title" at 386.302,-136.569 h1.78
  text "DESIGNED FOR:" at 385.032,-140.828 h1.14
  text ".PRJ_Customer" at 386.302,-144.384 h1.78
  text "FILE NAME:" at 385.032,-148.448 h1.14
  text ".PCB_File_Name_No_Path" at 386.302,-151.496 h1.78
  text "Texas Instruments (TI) and/or its licensors do not warrant the accuracy or completeness of this specification" at 258.807,-155.607 h1.14
  text "ENGINEER:" at 385.032,-155.814 h1.14
  text "LAYOUT BY:" at 423.259,-155.814 h1.14
  text "or any information contained therein. TI and/or its licensors do not warrant that this design will meet" at 257.664,-158.469 h1.14
  text ".PRJ_Engineer" at 386.302,-159.751 h1.78
  text ".PCB_Layout" at 424.542,-159.751 h1.78
  text "the specifications, will be suitable for your application or fit for any particular purpose, or will operate in" at 257.664,-161.33 h1.14
  text ".Layer_Name" at -10.344,-161.806 h1.52
  text "ALTIUM DESIGNER VERSION:" at 423.259,-163.688 h1.14
  text "an implementation. TI and/or its licensors do not warrant that the design is production worthy. You should" at 257.664,-164.192 h1.14
  text "completely validate and test your design implementation to confirm the system functionality for your application." at 258.807,-167.054 h1.14
  text ".print_Scale" at 386.302,-167.075 h1.78
  text ".Application_BuildNumber" at 424.542,-167.075 h1.78
  text "1" at 1.882,-173.493 h1.78
  text "2" at 86.354,-173.493 h1.78
  text "3" at 170.936,-173.493 h1.78
  text "4" at 255.645,-173.493 h1.78
  text "5" at 340.1,-173.493 h1.78
  text "6" at 424.809,-173.493 h1.78
M10 Fab Notes:
  drawing of 189 lines, arcs and shapes, not listed
  text "DESIGN INFORMATION" at 411.322,21.675 h1.52
  text "MIN. TRACK WIDTH:" at 394.95,18.319 h1.52
  text "8" at 422.794,18.32 h1.52
  text "MIL" at 426.725,18.319 h1.52
  text "MIN. CLEARANCE:" at 394.95,15.167 h1.52
  text "MIL" at 426.725,15.167 h1.52
  text "7.874" at 418.475,15.05 h1.52
  text "MIN. VIA PAD SIZE:" at 394.95,12.014 h1.52
  text "24" at 422.033,12.014 h1.52
  text "MIL" at 426.725,12.014 h1.52
  text "0.05mm (2MIL)" at 412.603,8.714 h1.52
  text "MINIMUM ANNULAR RING" at 386.587,8.506 h1.52
  text "EXTERNAL" at 430.586,8.506 h1.52
  text "PER" at 391.667,5.708 h1.52
  text "IPC-D-275 CLASS 2 LEVEL C" at 397.255,5.708 h1.52
  text "MIL, HOLES" at 435.056,3.156 h1.52
  text "+/-" at 425.088,2.938 h1.52
  text "+/-" at 446.78,2.938 h1.52
  text "REGISTRATION TOLERANCES:" at 386.587,2.911 h1.52
  text "METAL" at 417.062,2.911 h1.52
  text "5" at 431.697,2.911 h1.52
  text "3" at 452.855,2.911 h1.52
  text "MIL" at 455.808,2.911 h1.52
  text "HOLE SIZE TOLERANCE (UNLESS OTHERWISE SPECIFIED):" at 386.587,0.414 h1.52
  text "+/-" at 446.78,0.341 h1.52
  text "3" at 452.855,0.314 h1.52
  text "MIL" at 455.808,0.314 h1.52
  text "MATERIAL:" at 384.688,-3.182 h1.52
  text "FR-4 High Tg" at 409.744,-6.447 h1.52
  text "X" at 406.075,-6.65 h1.52
  text "FR-4" at 395.382,-6.765 h1.52
  text "OTHER" at 433.177,-6.765 h1.52
  text "62 MIL (1.6mm) +/-10%" at 403.512,-10.398 h1.52
  text "X" at 400.462,-10.46 h1.52
  text "THICKNESS:" at 386.587,-10.606 h1.52
  text "OTHER" at 436.149,-10.606 h1.52
  text "TOLERANCE:" at 386.587,-14.12 h1.52
  text "X" at 408.133,-14.12 h1.52
  text "ANSI IPC-6012 TYPE 3 CLASS 2" at 412.654,-14.12 h1.52
  text "OTHER +/-" at 412.654,-17.782 h1.52
  text "BOW & TWIST:" at 386.587,-21.47 h1.52
  text "X" at 408.133,-21.47 h1.52
  text "ANSI IPC-6012 TYPE 3 CLASS 2" at 412.654,-21.47 h1.52
  text "OTHER +/-" at 412.654,-25.196 h1.52
  text "DRILLING:" at 384.688,-28.514 h1.52
  text "NC_DRILL FILES" at 429.418,-31.185 h1.52
  text "REFERENCE:" at 386.587,-31.285 h1.52
  text "X" at 403.281,-31.288 h1.52
  text "AS SHOWN" at 407.802,-31.285 h1.52
  text "X" at 426.167,-31.285 h1.52
  text "OTHER" at 436.987,-34.899 h1.52
  text "PTH COPPER THICKNESS:" at 386.579,-34.988 h1.52
  text "X" at 415.516,-34.988 h1.52
  text "20-30 um" at 418.767,-34.988 h1.52
  text "BOARD FINISH:" at 384.688,-38.737 h1.52
  text "SILKSCREEN:" at 388.631,-41.534 h1.52
  text "X" at 412.959,-41.534 h1.52
  text "TOP" at 415.93,-41.534 h1.52
  text "X" at 425.913,-41.534 h1.52
  text "BOTTOM" at 428.91,-41.534 h1.52
  text "SILKSCREEN COLOR:" at 388.631,-45.476 h1.52
  text "X" at 412.933,-45.476 h1.52
  text "WHITE" at 415.93,-45.476 h1.52
  text "OTHER" at 428.91,-45.476 h1.52
  text "X" at 416.261,-49.12 h1.52
  text "GREEN" at 419.258,-49.12 h1.52
  text "OTHER" at 434.955,-49.12 h1.52
  text "SOLDER RESIST COLOR:" at 388.631,-49.294 h1.52
  text "X" at 416.261,-53.038 h1.52
  text "MATTE" at 419.258,-53.038 h1.52
  text "SEMI-GLOSS" at 434.943,-53.054 h1.52
  text "IMMERSION GOLD (ENIG)" at 411.638,-57.426 h1.52
  text "ENEPIG" at 445.611,-57.61 h1.52
  text "SURFACE FINISH:" at 384.688,-57.635 h1.52
  text "X" at 407.117,-57.635 h1.52
  text "IMM. TIN/SILVER OR EQUIV" at 393.059,-61.123 h1.52
  text "OTHER" at 429.418,-61.223 h1.52
  text "ARRAY/PANEL:" at 384.688,-65.169 h1.52
  text "CUT AND TRIM PER M1 BOARD OUTLINE" at 411.638,-65.378 h1.52
  text "N.C. ROUTE" at 411.638,-68.832 h1.52
  text "X" at 429.113,-68.832 h1.52
  text "V. SCORE" at 433.634,-68.832 h1.52
  text "CERTIFICATION:" at 384.688,-72.112 h1.52
  text "MATERIALS AND WORKMANSHIP FOR ALL PCBS" at 403.103,-72.112 h1.52
  text "TO MEET OR EXCEED THE REQUIREMENTS OF:" at 403.103,-74.501 h1.52
  text "X" at 393.896,-77.768 h1.52
  text "ANSI IPC-A-600F CLASS ->" at 397.147,-77.768 h1.52
  text "X" at 439.006,-77.768 h1.52
  text "2" at 441.8,-77.768 h1.52
  text "1" at 433.799,-77.806 h1.52
  text "3" at 450.792,-77.806 h1.52
  text "X" at 414.521,-81.519 h1.52
  text "RoHS" at 417.772,-81.519 h1.52
  text "OTHER" at 434.14,-81.519 h1.52
  text "PER ORDER" at 444.225,-81.519 h1.52
  text "ALL BOARDS MUST MEET OR EXCEED UL94-V0 REQUIREMENTS." at 385.388,-85.426 h1.52
  text "PCB MUST BEAR THE UL94V-0 UL REGISTERED MATERIAL ID NUMBER" at 385.388,-88.374 h1.52
  text "ADDITIONAL REQUIREMENTS:" at 384.688,-92.678 h1.52
  text "MICROSECTION:" at 386.587,-95.399 h1.52
  text "YES" at 409.593,-95.399 h1.52
  text "REQUIRED" at 431.475,-99.065 h1.52
  text "BARE BOARD ELEC. TEST:" at 386.587,-99.137 h1.52
  text "NONE" at 419.753,-99.137 h1.52
  text "X" at 428.478,-99.137 h1.52
  text "PER ORDER" at 446.512,-99.137 h1.52
  text "XX MIL VIAS REQUIRE NON-CONDUCTIVE FILL AND PLANARIZE" at 390.858,-104.343 h1.5
  text "XX MIL VIAS REQUIRE CONDUCTIVE FILL AND PLANARIZE" at 391.062,-106.984 h1.52
  text "OUTER XX MIL TRACES REQUIRE 50 OHM SINGLE-ENDED IMPEDANCE" at 391.037,-111.134 h1.47
  text "LAYER 2 & 3 (INNER LAYERS) XX MIL WIDE, XX MIL SPACE / TRACES REQUIRE 100 OHM DIFFERENTIAL IMPEDANCE" at 390.833,-117.121 h1.52
  text ".Layer_Name" at -10.344,-161.806 h1.52
M11 Gerber Information:
  lines w0.254: -32.417,-163.626 135.223,-163.626 ; -32.417,-158.462 135.274,-158.462 ; -32.417,-153.297 -32.417,-168.791 69.31,-168.791 135.274,-168.791 135.274,-153.297 -32.404,-153.297 -32.404,-168.791 7.614,-168.791 ; 30.194,-168.791 30.194,-153.297 ; 62.376,-158.462 62.376,-153.297 ; 83.712,-158.462 83.712,-153.297 ; 99.511,-168.956 99.511,-163.804
  text "ALL ARTWORK VIEWED FROM TOP SIDE" at -30.804,-156.654 h1.52
  text "BOARD #:" at 32.099,-156.654 h1.52
  text ".PRJ_Number" at 45.955,-156.654 h1.52
  text "REV:" at 67.405,-156.654 h1.52
  text ".PCB_Rev" at 74.809,-156.654 h1.52
  text "SVN REV:" at 88.69,-156.654 h1.52
  text ".VersionControl_RevNumber" at 101.543,-156.654 h1.52
  text "LAYER NAME =" at -30.804,-161.806 h1.52
  text "PLOT NAME =" at -30.804,-167.034 h1.52
  text ".plot_File_Name" at -10.344,-167.034 h1.52
  text "GENERATED    :" at 32.15,-167.034 h1.52
  text ".Print_Date" at 54.235,-167.034 h1.52
  text ".Print_Time" at 72.752,-167.034 h1.52
  text "TEXAS INSTRUMENTS" at 104.87,-167.034 h1.52
M12 Stackup:
  text ".Layer_Name" at -10.344,-161.806 h1.52
M13 Component Bodies Top:
  text ".Layer_Name" at -10.344,-161.806 h1.52
M14 Component Bodies Bottom:
  text ".Layer_Name" at -10.344,-161.806 h1.52
M15 Courtyards Top:
  text ".Layer_Name" at -10.344,-161.806 h1.52
M16 Courtyards Bottom:
  text ".Layer_Name" at -10.344,-161.806 h1.52
Drill Drawing:
  text ".Layer_Name" at -10.344,-161.806 h1.52
M17 Embedded Cavity:
  text ".Layer_Name" at -10.344,-161.806 h1.52
M18 Embedded Assembly:
  text ".Layer_Name" at -10.344,-161.806 h1.52
M19 Embedded Keepout:
  text ".Layer_Name" at -9,-161.5 h1.52

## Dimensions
-25,-150.16 to 0.4,-150.16 on M2 Board Dimensions
0,0 to 275,115 on M2 Board Dimensions
0,0 to 170,165 on M2 Board Dimensions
